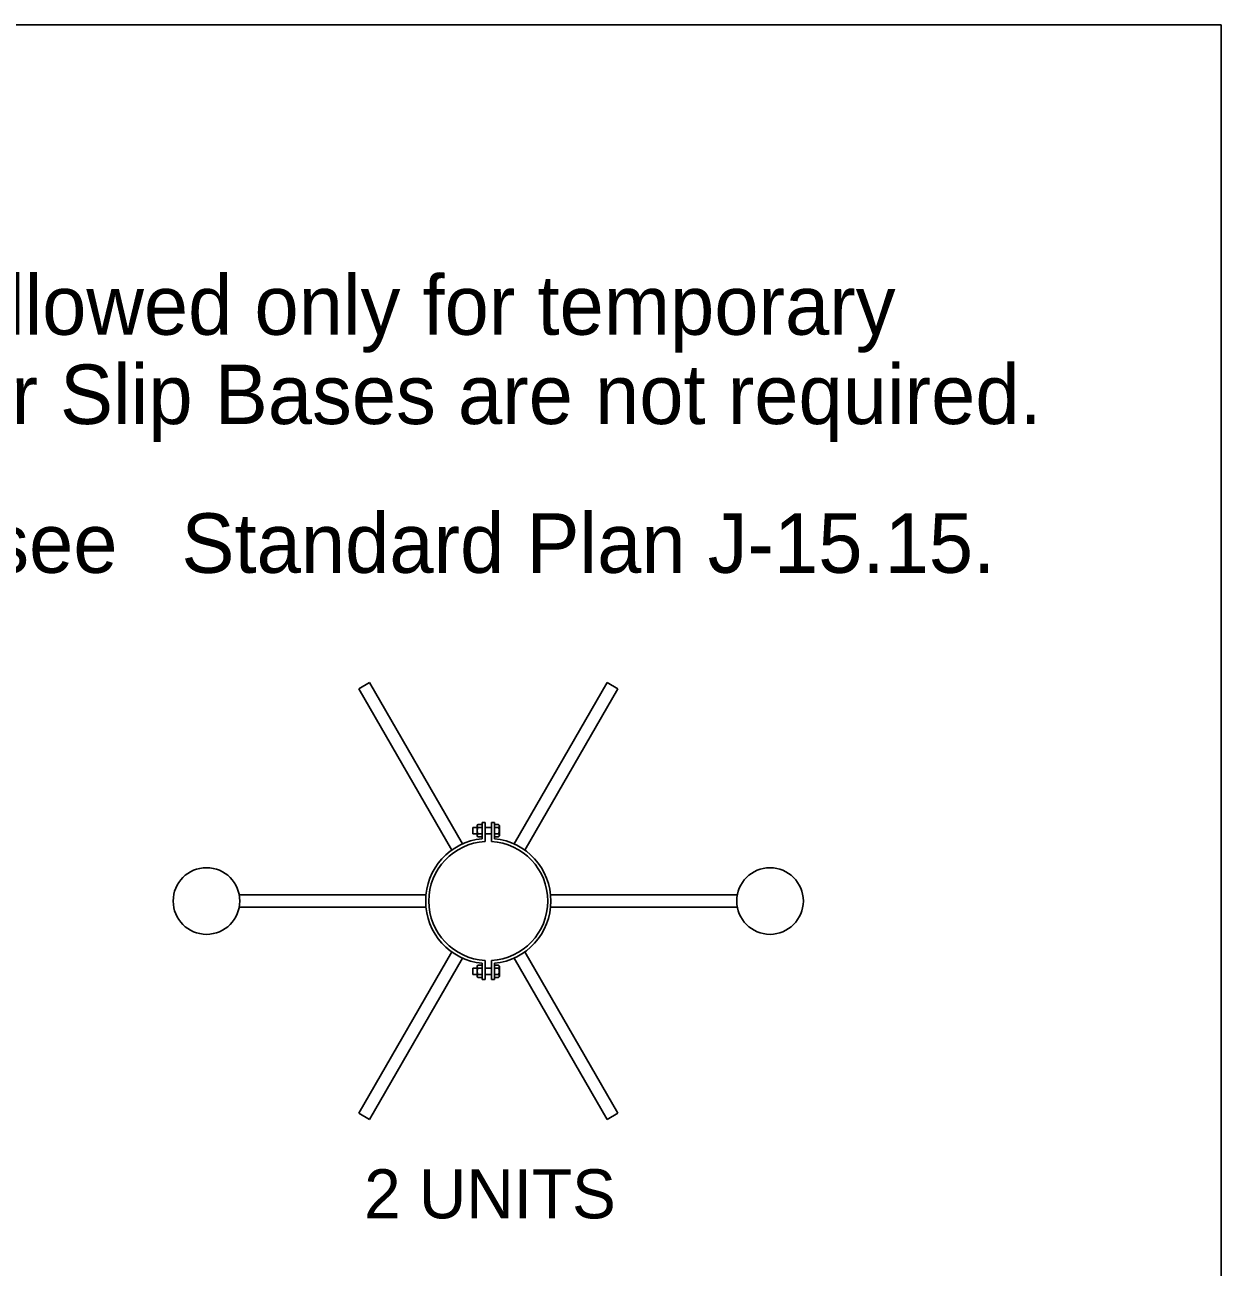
# Model space of a CAD drawing. Extents: x 99862 to 104211, y 98939 to 102076.
# Drawn here: x 102748.8 to 103151, y 101658.1 to 102075.5 of the extents above; entities that cross this region are included whole.
import ezdxf

# ---------------------------------------------------------------- set-up
doc = ezdxf.new("R2010")
doc.units = 0
for name, color, linetype in [('Level 1', 7, 'Continuous'), ('Level 2', 7, 'Continuous'), ('Level 20', 7, 'Continuous'), ('Level 4', 7, 'Continuous'), ('Level 60', 7, 'Continuous'), ('Level 7', 7, 'Continuous')]:
    doc.layers.add(name, color=color, linetype=linetype)

msp = doc.modelspace()

# ---------------------------------------------------------------- linework, layer by layer
at = {"layer": 'Level 1'}
msp.add_lwpolyline([(99862, 99999.5), (103151, 99999.5), (103151, 102075.5), (99862, 102075.5)], close=True, dxfattribs=at)
at = {"layer": 'Level 2'}
for p, q in [((102902.53, 101807.46), (102903.56, 101807.46)), ((102902.53, 101802.02), (102902.53, 101807.46)), ((102902.53, 101805.76), (102902.53, 101803.69)), ((102903.56, 101807.46), (102903.56, 101801.06)), ((102903.56, 101803.69), (102903.56, 101805.76)), ((102905.64, 101801.06), (102905.64, 101807.46)), ((102905.64, 101807.46), (102906.68, 101807.46)), ((102905.64, 101805.76), (102905.64, 101803.69)), ((102906.68, 101807.46), (102906.68, 101802.02)), ((102902.53, 101803.68), (102902.53, 101803.69)), ((102903.56, 101803.69), (102903.56, 101803.68)), ((102903.56, 101803.69), (102903.56, 101803.68)), ((102902.53, 101754.72), (102902.53, 101760.15)), ((102903.56, 101761.11), (102903.56, 101754.72)), ((102905.64, 101754.72), (102905.64, 101761.11)), ((102906.68, 101760.15), (102906.68, 101754.72)), ((102903.56, 101754.72), (102902.53, 101754.72)), ((102906.68, 101754.72), (102905.64, 101754.72))]:
    msp.add_line(p, q, dxfattribs=at)
for radius, start, end in [(21.04, 95.6605, 264.3395), (21.04, 275.6605, 84.3395), (20, 92.9736, 267.0264), (20, 272.9736, 87.0264)]:
    msp.add_arc((102904.6, 101781.09), radius, start, end, dxfattribs=at)
at = {"layer": 'Level 4'}
for p, q in [((102861.04, 101852.4), (102864.63, 101854.47)), ((102861.04, 101852.4), (102864.63, 101854.47)), ((102861.04, 101852.4), (102892.34, 101798.18)), ((102864.63, 101854.47), (102864.63, 101854.47)), ((102864.63, 101854.47), (102864.63, 101854.47)), ((102895.93, 101800.25), (102864.63, 101854.47)), ((102944.57, 101854.47), (102913.27, 101800.25)), ((102916.87, 101798.18), (102948.17, 101852.4)), ((102944.57, 101854.47), (102948.17, 101852.4)), ((102944.57, 101854.47), (102948.17, 101852.4)), ((102948.17, 101852.4), (102948.17, 101852.4)), ((102948.17, 101852.4), (102948.17, 101852.4)), ((102883.67, 101783.16), (102820.87, 101783.16)), ((102988.33, 101783.16), (102925.54, 101783.16)), ((102820.87, 101779.01), (102883.67, 101779.01)), ((102925.54, 101779.01), (102988.33, 101779.01)), ((102892.34, 101763.99), (102861.04, 101709.78)), ((102864.63, 101707.7), (102895.93, 101761.92)), ((102913.27, 101761.92), (102944.57, 101707.7)), ((102948.17, 101709.78), (102916.87, 101763.99)), ((102864.63, 101707.7), (102861.04, 101709.78)), ((102861.04, 101709.78), (102861.04, 101709.78)), ((102864.63, 101707.7), (102861.04, 101709.78)), ((102861.04, 101709.78), (102861.04, 101709.78)), ((102948.17, 101709.78), (102944.57, 101707.7)), ((102948.17, 101709.78), (102944.57, 101707.7)), ((102944.57, 101707.7), (102944.57, 101707.7)), ((102944.57, 101707.7), (102944.57, 101707.7))]:
    msp.add_line(p, q, dxfattribs=at)
for centre in [(102809.87, 101781.09), (102999.33, 101781.09)]:
    msp.add_circle(centre, 11.2, dxfattribs=at)
at = {"layer": 'Level 60'}
msp.add_line((103151, 102075.5), (103151, 102075.5), dxfattribs=at)
at = {"layer": 'Level 7'}
for p, q in [((102899.39, 101805.75), (102899.39, 101803.7)), ((102899.39, 101805.75), (102899.39, 101803.7)), ((102900.87, 101805.75), (102899.39, 101805.75)), ((102901.14, 101806.81), (102900.87, 101806.5)), ((102900.87, 101806.5), (102900.87, 101802.96)), ((102900.87, 101802.96), (102900.87, 101806.5)), ((102900.87, 101802.96), (102900.87, 101806.5)), ((102900.87, 101802.96), (102900.87, 101806.49)), ((102900.87, 101805.75), (102900.87, 101803.7)), ((102900.87, 101805.75), (102900.87, 101803.7)), ((102901.14, 101806.81), (102902.53, 101806.81)), ((102901.14, 101805.77), (102902.53, 101805.77)), ((102905.64, 101805.75), (102903.56, 101805.75)), ((102908.06, 101806.81), (102906.68, 101806.81)), ((102908.06, 101805.77), (102906.68, 101805.77)), ((102908.34, 101806.5), (102908.06, 101806.81)), ((102908.34, 101806.5), (102908.34, 101802.96)), ((102908.34, 101802.96), (102908.34, 101806.5)), ((102908.34, 101802.96), (102908.34, 101806.5)), ((102908.34, 101802.96), (102908.34, 101806.49)), ((102899.39, 101803.7), (102899.39, 101803.69)), ((102899.39, 101803.7), (102899.39, 101803.69)), ((102899.39, 101803.7), (102899.39, 101803.7)), ((102899.39, 101803.69), (102899.39, 101803.69)), ((102899.39, 101803.69), (102900.87, 101803.69)), ((102900.87, 101805.74), (102900.87, 101803.69)), ((102900.87, 101802.96), (102901.14, 101802.64)), ((102901.14, 101803.69), (102902.53, 101803.69)), ((102901.14, 101802.64), (102902.53, 101802.64)), ((102902.53, 101802.64), (102902.53, 101802.63)), ((102903.56, 101803.7), (102905.64, 101803.7)), ((102903.56, 101803.69), (102905.64, 101803.69)), ((102908.06, 101803.69), (102906.68, 101803.69)), ((102908.06, 101802.64), (102906.68, 101802.64)), ((102908.06, 101802.64), (102908.34, 101802.96)), ((102899.39, 101758.48), (102899.39, 101758.47)), ((102899.39, 101758.48), (102899.39, 101758.47)), ((102900.87, 101758.48), (102899.39, 101758.48)), ((102899.39, 101758.47), (102899.39, 101756.42)), ((102899.39, 101758.47), (102899.39, 101756.42)), ((102899.39, 101756.42), (102899.39, 101756.42)), ((102899.39, 101756.42), (102900.87, 101756.42)), ((102901.14, 101759.53), (102900.87, 101759.22)), ((102900.87, 101755.68), (102900.87, 101759.22)), ((102900.87, 101759.22), (102900.87, 101755.68)), ((102900.87, 101758.48), (102900.87, 101756.43)), ((102900.87, 101758.47), (102900.87, 101756.42)), ((102900.87, 101758.47), (102900.87, 101756.42)), ((102900.87, 101755.68), (102901.14, 101755.36)), ((102901.14, 101759.53), (102902.53, 101759.53)), ((102901.14, 101758.49), (102902.53, 101758.49)), ((102901.14, 101756.41), (102902.53, 101756.41)), ((102905.64, 101758.48), (102903.56, 101758.48)), ((102903.56, 101756.42), (102905.64, 101756.42)), ((102908.06, 101759.53), (102906.68, 101759.53)), ((102908.06, 101758.49), (102906.68, 101758.49)), ((102908.06, 101756.41), (102906.68, 101756.41)), ((102908.34, 101759.22), (102908.06, 101759.53)), ((102908.06, 101755.36), (102908.34, 101755.68)), ((102908.34, 101759.22), (102908.34, 101755.68)), ((102908.34, 101755.68), (102908.34, 101759.22)), ((102908.34, 101755.68), (102908.34, 101759.22)), ((102901.14, 101755.36), (102902.53, 101755.36)), ((102908.06, 101755.36), (102906.68, 101755.36))]:
    msp.add_line(p, q, dxfattribs=at)
for points in [[(102901.14, 101806.81), (102901.07, 101806.73), (102901.01, 101806.64), (102900.92, 101806.47), (102900.9, 101806.38), (102900.9, 101806.11), (102901, 101805.93), (102901.14, 101805.77)], [(102901.14, 101803.69), (102901.07, 101803.85), (102901.01, 101804.02), (102900.92, 101804.37), (102900.9, 101804.54), (102900.9, 101804.91), (102900.92, 101805.09), (102901.01, 101805.43), (102901.07, 101805.6), (102901.14, 101805.77)], [(102908.06, 101806.81), (102908.14, 101806.73), (102908.2, 101806.64), (102908.28, 101806.47), (102908.31, 101806.38), (102908.31, 101806.11), (102908.21, 101805.93), (102908.06, 101805.77)], [(102908.06, 101803.69), (102908.14, 101803.85), (102908.2, 101804.02), (102908.28, 101804.37), (102908.31, 101804.54), (102908.31, 101804.91), (102908.28, 101805.09), (102908.2, 101805.43), (102908.14, 101805.6), (102908.06, 101805.77)], [(102901.14, 101803.69), (102901.07, 101803.6), (102901.01, 101803.52), (102900.92, 101803.35), (102900.9, 101803.25), (102900.9, 101802.99), (102901, 101802.81), (102901.14, 101802.64)], [(102908.06, 101803.69), (102908.14, 101803.6), (102908.2, 101803.52), (102908.28, 101803.35), (102908.31, 101803.25), (102908.31, 101802.99), (102908.21, 101802.81), (102908.06, 101802.64)], [(102901.14, 101759.53), (102901.07, 101759.45), (102901.01, 101759.36), (102900.92, 101759.19), (102900.9, 101759.1), (102900.9, 101758.83), (102901, 101758.65), (102901.14, 101758.49)], [(102901.14, 101756.41), (102901.07, 101756.57), (102901.01, 101756.74), (102900.92, 101757.09), (102900.9, 101757.26), (102900.9, 101757.63), (102900.92, 101757.81), (102901.01, 101758.15), (102901.07, 101758.32), (102901.14, 101758.49)], [(102901.14, 101756.41), (102901.07, 101756.32), (102901.01, 101756.24), (102900.92, 101756.07), (102900.9, 101755.97), (102900.9, 101755.71), (102901, 101755.53), (102901.14, 101755.36)], [(102908.06, 101759.53), (102908.14, 101759.45), (102908.2, 101759.36), (102908.28, 101759.19), (102908.31, 101759.1), (102908.31, 101758.83), (102908.21, 101758.65), (102908.06, 101758.49)], [(102908.06, 101756.41), (102908.14, 101756.57), (102908.2, 101756.74), (102908.28, 101757.09), (102908.31, 101757.26), (102908.31, 101757.63), (102908.28, 101757.81), (102908.2, 101758.15), (102908.14, 101758.32), (102908.06, 101758.49)], [(102908.06, 101756.41), (102908.14, 101756.32), (102908.2, 101756.24), (102908.28, 101756.07), (102908.31, 101755.97), (102908.31, 101755.71), (102908.21, 101755.53), (102908.06, 101755.36)]]:
    msp.add_open_spline(points, degree=3, dxfattribs=at)

# ---------------------------------------------------------------- texts
at = {"layer": 'Level 20'}
for s, height, p in [('Timber luminaire supports are allowed only for temporary', 20, (102365.2, 101971.36)), ('installations where breakaway or Slip Bases are not required.', 20, (102365.2, 101941.36)), ('When down guys are required, see', 20, (102365.2, 101891.36)), (' Standard Plan J-15.15.', 20, (102794.02, 101891.36)), ('2 UNITS', 16.5, (102862.89, 101674.45))]:
    msp.add_text(s, height=height, dxfattribs=at).set_placement(p)

doc.saveas('drawing.dxf')
